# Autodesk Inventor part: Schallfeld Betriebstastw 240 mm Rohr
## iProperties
Shininess: 20.0
Length Units: 11269
Angle Units: 11279
Time Units: 11290
Mass Units: 11283
Length Display Precision: 2
Angle Display Precision: 2
Part Number: Schallfeld Betriebstastw 240 mm Rohr
Material: Lexan (klar)
Document SubType Name: Modellieren
Checked By: Alves
Created: 2005-08
Designer: Grube
Manufacturer: Standard
Standards Organization: Custom
Description: Schallfeld 0,24m
Density: 0.0
Volumn: 0.0
Area: 0.0
PropertySet Name: Model Information
Control State: 0
Master: False
Checked Out: False
Last Check In By: Kramp
Last Check In Date: 2005-08-11
ME: ST
Comments: keine Bemerkung
Title: Schallfelder
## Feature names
1. Rohr [Revolution]
